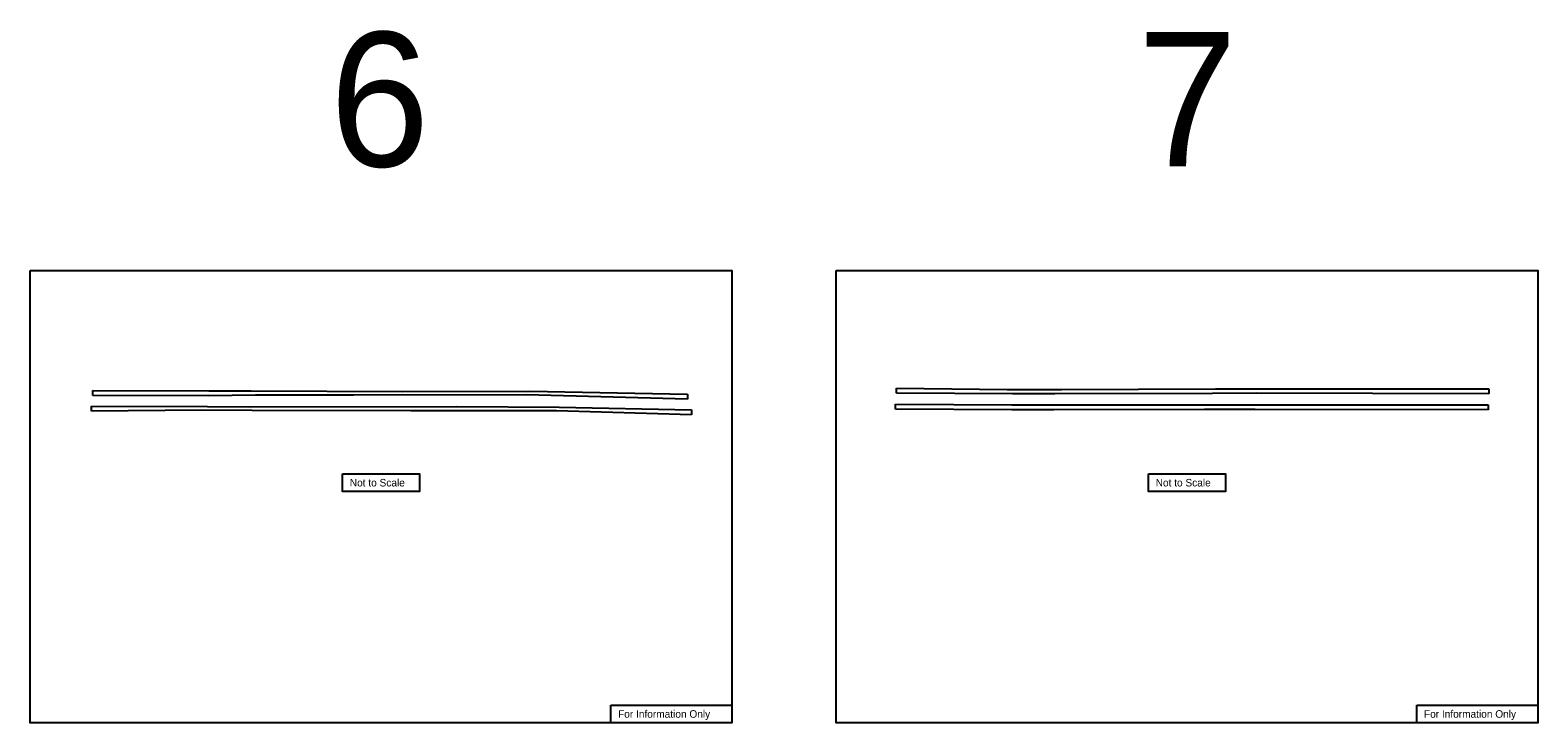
# Model space of a CAD drawing. Extents: x 10133 to 81668, y 7924 to 12255.
# Drawn here: x 28133 to 34868, y 7924 to 11018 of the extents above; entities that cross this region are included whole.
import ezdxf

# ---------------------------------------------------------------- set-up
doc = ezdxf.new("R2010")
doc.units = 0
for name, color, linetype in [('RasterAttachment', 7, 'Continuous'), ('SheetBorder', 7, 'Continuous'), ('SheetText', 7, 'Continuous')]:
    doc.layers.add(name, color=color, linetype=linetype)

msp = doc.modelspace()

# ---------------------------------------------------------------- linework, layer by layer
at = {"layer": 'RasterAttachment'}
for p, q in [((28412.1, 9386.9), (28412.1, 9409.2)), ((28412.1, 9409.2), (28930.7, 9407.4)), ((28930.7, 9385.1), (28412.1, 9386.9)), ((28930.7, 9407.4), (29119.5, 9406.7)), ((29139.3, 9387.7), (28930.7, 9385.1)), ((29119.5, 9406.7), (29797.6, 9404.4)), ((29576.9, 9387.3), (29139.3, 9387.7)), ((30349.5, 9388.7), (29576.9, 9387.3)), ((29797.6, 9404.4), (30364.3, 9405.2)), ((31068.9, 9370.1), (30349.5, 9388.7)), ((30364.3, 9405.2), (31068.9, 9392.4)), ((31068.9, 9392.4), (31068.9, 9370.1)), ((32002.6, 9396.1), (32002.6, 9418.3)), ((32002.6, 9418.3), (32496.9, 9413.4)), ((32521.1, 9394.2), (32002.6, 9396.1)), ((32496.9, 9413.4), (32739.5, 9413.7)), ((32710, 9393.6), (32521.1, 9394.2)), ((33413.8, 9394.8), (32710, 9393.6)), ((32739.5, 9413.7), (33427, 9415.7)), ((33609.4, 9396), (33413.8, 9394.8)), ((33427, 9415.7), (33624.8, 9415.3)), ((34649.1, 9393.9), (33609.4, 9396)), ((33624.8, 9415.3), (34649.1, 9416.1)), ((34649.1, 9416.1), (34649.1, 9393.9)), ((28405.9, 9316.4), (28405.9, 9338.7)), ((28405.9, 9338.7), (28924.5, 9336.9)), ((28899.7, 9320.2), (28405.9, 9316.4)), ((29124.7, 9318.8), (28899.7, 9320.2)), ((28924.5, 9336.9), (29113.3, 9336.2)), ((29113.3, 9336.2), (30038.3, 9336.7)), ((29833.5, 9318), (29124.7, 9318.8)), ((30484.4, 9317.5), (29833.5, 9318)), ((30038.3, 9336.7), (30495.2, 9333.9)), ((31086.6, 9299.6), (30484.4, 9317.5)), ((30495.2, 9333.9), (31086.6, 9321.9)), ((31086.6, 9321.9), (31086.6, 9299.6)), ((31998.6, 9324.7), (31998.6, 9346.9)), ((31998.6, 9346.9), (32517.2, 9345.1)), ((32517.2, 9322.8), (31998.6, 9324.7)), ((32517.2, 9345.1), (32706, 9344.5)), ((32706, 9322.2), (32517.2, 9322.8)), ((32706, 9344.5), (33377.3, 9344.7)), ((33378.6, 9323.9), (32706, 9322.2)), ((33377.3, 9344.7), (33649.9, 9344.1)), ((33605.4, 9323.2), (33378.6, 9323.9)), ((34645.2, 9322.5), (33605.4, 9323.2)), ((33649.9, 9344.1), (34645.2, 9344.7)), ((34645.2, 9344.7), (34645.2, 9322.5))]:
    msp.add_line(p, q, dxfattribs=at)
at = {"layer": 'SheetBorder'}
for points in [[(28132.5, 9944), (31267.5, 9944), (31267.5, 7924), (28132.5, 7924)], [(31732.5, 9944), (34867.5, 9944), (34867.5, 7924), (31732.5, 7924)]]:
    msp.add_lwpolyline(points, close=True, dxfattribs=at)
at = {"layer": 'SheetText'}
for points in [[(29528.5, 9036.5), (29871.6, 9036.5), (29871.6, 8957.1), (29528.5, 8957.1)], [(33128.5, 9036.5), (33471.6, 9036.5), (33471.6, 8957.1), (33128.5, 8957.1)], [(30727, 8003.4), (31267.5, 8003.4), (31267.5, 7924), (30727, 7924)], [(34327, 8003.4), (34867.5, 8003.4), (34867.5, 7924), (34327, 7924)]]:
    msp.add_lwpolyline(points, close=True, dxfattribs=at)

# ---------------------------------------------------------------- texts
for s, height, p in [('6', 600, (29470.4, 10409.2)), ('7', 600, (33079.7, 10409.2)), ('Not to Scale', 33.75, (29560.4, 8979.9)), ('Not to Scale', 33.75, (33160.4, 8979.9)), ('For Information Only', 33.75, (30758.8, 7946.8)), ('For Information Only', 33.75, (34358.8, 7946.8))]:
    msp.add_text(s, height=height, dxfattribs=at).set_placement(p)

doc.saveas('drawing.dxf')
